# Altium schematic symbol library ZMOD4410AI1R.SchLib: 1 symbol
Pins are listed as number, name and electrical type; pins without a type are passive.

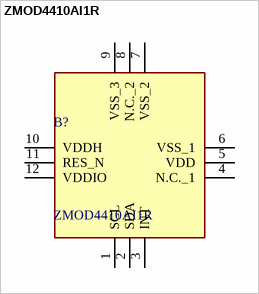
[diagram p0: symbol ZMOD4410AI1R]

## ZMOD4410AI1R
designator B?
The ZMOD4410 gas sensor module is an easily integrated firmware configurable architecture enabling multiple sensing solutions with a common hardware platform. Simply download one of the firmware libraries that best supports your application from the Renesas website and integrate it with your host microcontroller. The JEDEC JESD47 qualified device supports 10+ years of life, supporting your indoor air quality (IAQ) application designed for detecting total volatile organic compounds (TVOCs), estimating CO2, a; Manufacturer_Name: Renesas Electronics; Geometry.Height: 0.77mm
footprint ZMOD4410AI1R
pins: 1 SCL, 2 SDA, 3 INT, 4 N.C._1, 5 VDD, 6 VSS_1, 7 VSS_2, 8 N.C._2, 9 VSS_3, 10 VDDH, 11 RES_N, 12 VDDIO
